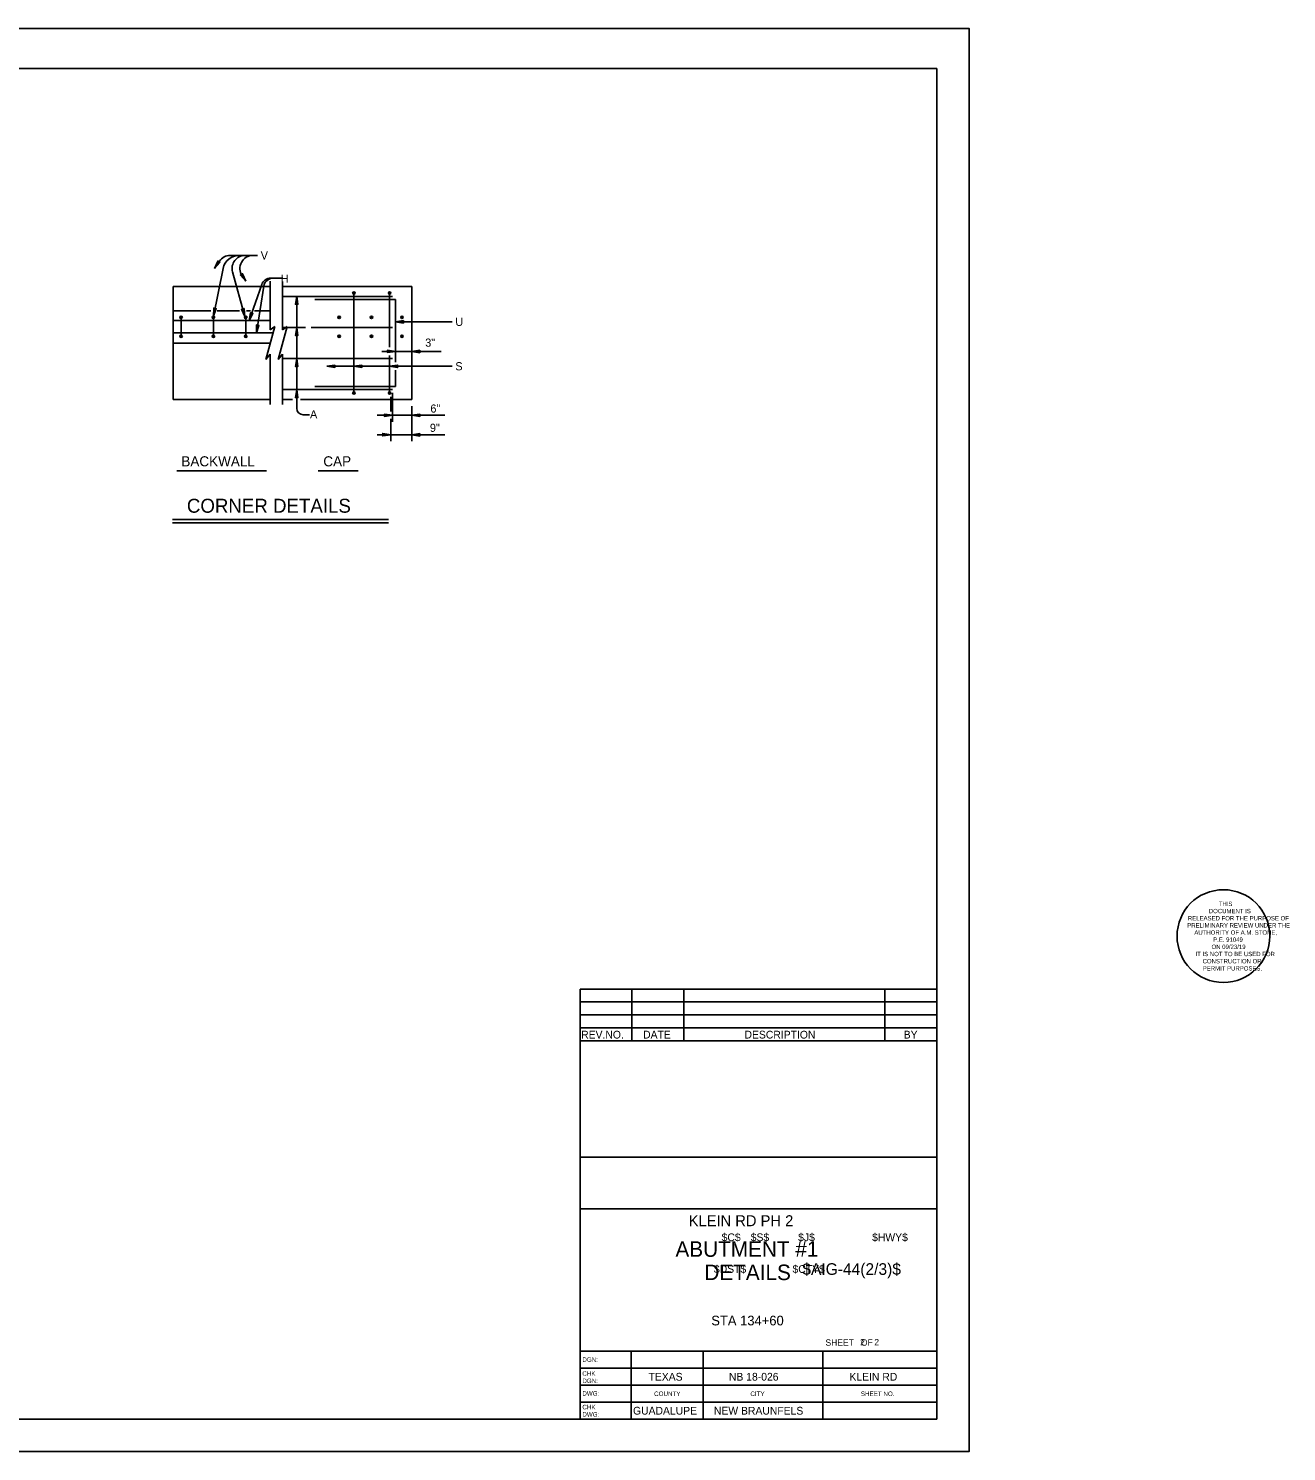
# Model space of a CAD drawing. Extents: x 970 to 1074, y 989 to 1045.
# Drawn here: x 1054.46 to 1073.91, y 997.81 to 1019.81 of the extents above; entities that cross this region are included whole.
import ezdxf

# ---------------------------------------------------------------- set-up
doc = ezdxf.new("R2010")
doc.units = 0
for name, color, linetype in [('BORD_lines_major', 7, 'Continuous'), ('BORD_lines_minor', 7, 'Continuous'), ('BORD_text_large_1', 7, 'Continuous'), ('BORD_text_large_2', 7, 'Continuous'), ('BORD_text_small_1', 7, 'Continuous'), ('BORD_text_small_3', 7, 'Continuous'), ('BORD_text_small_proj', 7, 'Continuous'), ('C-MS-ANNO-TTLB-STMP', 7, 'Continuous'), ('D_BATCH_PLOT', 7, 'Continuous'), ('D_SHEET', 7, 'Continuous'), ('D_SHEET_NUM_CODE', 7, 'Continuous'), ('D_SHEET_TXT_SUB_CODE', 7, 'Continuous'), ('Working Level 1', 7, 'Continuous')]:
    doc.layers.add(name, color=color, linetype=linetype)

msp = doc.modelspace()

# ---------------------------------------------------------------- linework, layer by layer
at = {"layer": 'BORD_lines_major'}
for p, q in [((1037.413, 1019.195), (1068.5, 1019.195)), ((1068.5, 998.313), (1068.5, 1019.195)), ((1037.413, 998.313), (1068.5, 998.313))]:
    msp.add_line(p, q, dxfattribs=at)
at = {"layer": 'BORD_lines_minor'}
for p, q in [((1062.988, 1004.963), (1068.5, 1004.963)), ((1062.988, 1004.163), (1062.988, 1004.963)), ((1063.788, 1004.963), (1063.788, 1004.163)), ((1064.588, 1004.963), (1064.588, 1004.163)), ((1067.7, 1004.163), (1067.7, 1004.963)), ((1062.988, 1004.763), (1068.5, 1004.763)), ((1062.988, 1004.563), (1068.5, 1004.563)), ((1062.988, 1004.363), (1068.5, 1004.363)), ((1062.988, 1004.163), (1068.5, 1004.163)), ((1062.988, 1004.163), (1062.988, 1002.363)), ((1062.988, 1002.363), (1068.5, 1002.363)), ((1062.988, 1002.363), (1062.988, 998.313)), ((1062.988, 1001.563), (1068.5, 1001.563)), ((1062.988, 999.363), (1068.5, 999.363)), ((1063.776, 999.363), (1063.776, 998.313)), ((1064.888, 999.363), (1064.888, 998.313)), ((1066.738, 999.363), (1066.738, 998.313)), ((1062.988, 999.1), (1068.5, 999.1)), ((1062.988, 998.838), (1068.5, 998.838)), ((1062.988, 998.575), (1068.5, 998.575))]:
    msp.add_line(p, q, dxfattribs=at)
at = {"layer": 'C-MS-ANNO-TTLB-STMP'}
msp.add_circle((1072.934, 1005.781), 0.717, dxfattribs=at)
at = {"layer": 'D_BATCH_PLOT'}
msp.add_lwpolyline([(1035, 997.813), (1069, 997.813), (1069, 1019.813), (1035, 1019.813)], close=True, dxfattribs=at)
at = {"layer": 'D_SHEET'}
for p, q in [((1035, 1019.813), (1069, 1019.813)), ((1069, 997.813), (1069, 1019.813)), ((1035, 997.813), (1069, 997.813))]:
    msp.add_line(p, q, dxfattribs=at)
at = {"layer": 'Working Level 1'}
for p, q in [((1057.33, 1016.103), (1057.409, 1016.218)), ((1057.574, 1016.304), (1057.995, 1016.304)), ((1057.315, 1015.365), (1057.466, 1016.104)), ((1057.611, 1016.051), (1057.803, 1015.359)), ((1057.818, 1015.908), (1057.761, 1015.991)), ((1056.692, 1014.075), (1056.692, 1015.825)), ((1058.192, 1015.825), (1056.692, 1015.825)), ((1057.867, 1015.296), (1058.062, 1015.854)), ((1057.979, 1015.105), (1058.094, 1015.828)), ((1058.192, 1015.155), (1058.192, 1015.904)), ((1058.388, 1015.954), (1058.242, 1015.954)), ((1058.385, 1015.155), (1058.385, 1015.903)), ((1058.385, 1015.825), (1060.385, 1015.825)), ((1060.385, 1014.075), (1060.385, 1015.825)), ((1058.385, 1015.671), (1060.085, 1015.671)), ((1058.604, 1013.941), (1058.604, 1015.671)), ((1058.881, 1015.621), (1060.131, 1015.621)), ((1059.487, 1015.721), (1059.487, 1014.18)), ((1060.039, 1015.721), (1060.039, 1014.885)), ((1060.131, 1015.621), (1060.131, 1014.656)), ((1057.276, 1015.45), (1056.692, 1015.45)), ((1056.817, 1015.055), (1056.817, 1015.346)), ((1057.317, 1015.055), (1057.317, 1015.346)), ((1057.718, 1015.45), (1057.374, 1015.45)), ((1057.817, 1015.055), (1057.817, 1015.346)), ((1057.891, 1015.45), (1057.826, 1015.45)), ((1058.192, 1015.45), (1057.949, 1015.45)), ((1058.192, 1015.296), (1056.692, 1015.296)), ((1058.237, 1015.105), (1056.692, 1015.105)), ((1058.126, 1014.695), (1058.264, 1015.207)), ((1058.264, 1015.207), (1058.192, 1015.155)), ((1058.319, 1014.695), (1058.457, 1015.207)), ((1058.457, 1015.207), (1058.385, 1015.155)), ((1058.385, 1015.191), (1058.435, 1015.191)), ((1058.453, 1015.191), (1058.74, 1015.191)), ((1058.829, 1015.191), (1060.085, 1015.191)), ((1060.131, 1015.277), (1061.009, 1015.277)), ((1058.195, 1014.95), (1056.692, 1014.95)), ((1058.192, 1014.775), (1058.126, 1014.695)), ((1058.192, 1013.997), (1058.192, 1014.775)), ((1058.385, 1014.775), (1058.319, 1014.695)), ((1058.385, 1013.997), (1058.385, 1014.775)), ((1058.385, 1014.71), (1060.085, 1014.71)), ((1060.835, 1014.82), (1059.92, 1014.82)), ((1060.039, 1014.757), (1060.039, 1014.18)), ((1059.068, 1014.591), (1061.009, 1014.591)), ((1060.131, 1014.532), (1060.131, 1014.28)), ((1058.385, 1014.23), (1060.085, 1014.23)), ((1058.881, 1014.28), (1060.131, 1014.28)), ((1058.192, 1014.075), (1056.692, 1014.075)), ((1058.385, 1014.075), (1058.539, 1014.075)), ((1058.663, 1014.075), (1060.385, 1014.075)), ((1060.058, 1014.12), (1060.058, 1013.893)), ((1060.085, 1014.182), (1060.085, 1013.732)), ((1058.704, 1013.841), (1058.803, 1013.841)), ((1060.892, 1013.832), (1059.848, 1013.832)), ((1060.058, 1013.776), (1060.058, 1013.432)), ((1060.385, 1013.975), (1060.385, 1013.432)), ((1060.892, 1013.532), (1059.848, 1013.532)), ((1056.751, 1012.975), (1058.135, 1012.975)), ((1058.933, 1012.975), (1059.555, 1012.975)), ((1056.681, 1012.221), (1060.025, 1012.221)), ((1056.681, 1012.171), (1060.025, 1012.171))]:
    msp.add_line(p, q, dxfattribs=at)
for points in [[(1057.33, 1016.103), (1057.383, 1016.216), (1057.415, 1016.194)], [(1057.818, 1015.908), (1057.765, 1016.021), (1057.733, 1015.999)], [(1058.604, 1015.671), (1058.584, 1015.549), (1058.623, 1015.549)], [(1057.315, 1015.365), (1057.359, 1015.481), (1057.321, 1015.489)], [(1057.803, 1015.359), (1057.79, 1015.483), (1057.752, 1015.472)], [(1057.867, 1015.296), (1057.926, 1015.405), (1057.89, 1015.418)], [(1057.979, 1015.105), (1058.018, 1015.222), (1057.98, 1015.229)], [(1058.604, 1015.191), (1058.584, 1015.068), (1058.623, 1015.068)], [(1060.131, 1015.277), (1060.253, 1015.257), (1060.253, 1015.296)], [(1058.604, 1014.71), (1058.584, 1014.588), (1058.623, 1014.588)], [(1060.131, 1014.82), (1060.008, 1014.84), (1060.008, 1014.801)], [(1060.385, 1014.82), (1060.507, 1014.8), (1060.507, 1014.838)], [(1059.068, 1014.591), (1059.191, 1014.571), (1059.191, 1014.61)], [(1059.487, 1014.591), (1059.609, 1014.571), (1059.609, 1014.61)], [(1060.039, 1014.591), (1060.162, 1014.571), (1060.162, 1014.61)], [(1058.604, 1014.23), (1058.584, 1014.107), (1058.623, 1014.107)], [(1060.085, 1013.832), (1059.962, 1013.852), (1059.962, 1013.813)], [(1060.385, 1013.832), (1060.507, 1013.812), (1060.507, 1013.851)], [(1060.058, 1013.532), (1059.935, 1013.552), (1059.935, 1013.513)], [(1060.385, 1013.532), (1060.507, 1013.512), (1060.507, 1013.551)]]:
    msp.add_lwpolyline(points, close=True, dxfattribs=at)
for centre, radius in [((1059.487, 1015.721), 0.0187), ((1060.039, 1015.721), 0.0187), ((1059.487, 1015.721), 0.0117), ((1059.487, 1015.721), 0.00469), ((1060.039, 1015.721), 0.0117), ((1060.039, 1015.721), 0.00469), ((1056.816, 1015.346), 0.0187), ((1056.816, 1015.346), 0.0117), ((1056.816, 1015.346), 0.00469), ((1057.316, 1015.346), 0.0187), ((1057.316, 1015.346), 0.0117), ((1057.316, 1015.346), 0.00469), ((1057.816, 1015.346), 0.0187), ((1057.816, 1015.346), 0.0117), ((1057.816, 1015.346), 0.00469), ((1059.26, 1015.346), 0.0187), ((1059.26, 1015.346), 0.0117), ((1059.26, 1015.346), 0.00469), ((1059.76, 1015.346), 0.0187), ((1059.76, 1015.346), 0.0117), ((1059.76, 1015.346), 0.00469), ((1060.231, 1015.346), 0.0187), ((1060.231, 1015.346), 0.0117), ((1060.231, 1015.346), 0.00469), ((1056.816, 1015.055), 0.0187), ((1056.816, 1015.055), 0.0117), ((1056.816, 1015.055), 0.00469), ((1057.316, 1015.055), 0.0187), ((1057.316, 1015.055), 0.0117), ((1057.316, 1015.055), 0.00469), ((1057.816, 1015.055), 0.0187), ((1057.816, 1015.055), 0.0117), ((1057.816, 1015.055), 0.00469), ((1059.26, 1015.055), 0.0187), ((1059.26, 1015.055), 0.0117), ((1059.26, 1015.055), 0.00469), ((1059.76, 1015.055), 0.0187), ((1059.76, 1015.055), 0.0117), ((1059.76, 1015.055), 0.00469), ((1060.231, 1015.055), 0.0187), ((1060.231, 1015.055), 0.0187), ((1060.231, 1015.055), 0.0117), ((1060.231, 1015.055), 0.0117), ((1060.231, 1015.055), 0.00469), ((1060.231, 1015.055), 0.00469), ((1059.487, 1014.179), 0.0187), ((1060.039, 1014.179), 0.0187), ((1059.487, 1014.179), 0.0117), ((1059.487, 1014.179), 0.00469), ((1060.039, 1014.179), 0.0117), ((1060.039, 1014.179), 0.00469)]:
    msp.add_circle(centre, radius, dxfattribs=at)
for centre, radius, start, end in [((1057.574, 1016.104), 0.2, 90, 145.4917), ((1057.711, 1016.054), 0.25, 90, 168.4552), ((1057.804, 1016.104), 0.2, 90, 195.5006), ((1057.925, 1016.104), 0.2, 90, 214.524), ((1058.203, 1015.804), 0.15, 90, 160.7438), ((1058.242, 1015.804), 0.15, 90, 170.9957), ((1058.704, 1013.941), 0.1, 180, 270)]:
    msp.add_arc(centre, radius, start, end, dxfattribs=at)

# ---------------------------------------------------------------- texts
at = {"layer": 'BORD_lines_minor'}
for s, p in [('REV.NO.', (1063.002, 1004.198)), ('DATE', (1063.96, 1004.198)), ('DESCRIPTION', (1065.528, 1004.198)), ('BY', (1067.99, 1004.198))]:
    msp.add_text(s, height=0.12, rotation=359.9834, dxfattribs=at).set_placement(p)
msp.add_text('KLEIN RD PH 2', height=0.17, dxfattribs=at).set_placement((1064.665, 1001.296))
at = {"layer": 'BORD_text_large_1'}
for s, p in [('ABUTMENT #1', (1064.46, 1000.823)), ('DETAILS', (1064.907, 1000.463))]:
    msp.add_text(s, height=0.24, dxfattribs=at).set_placement(p)
at = {"layer": 'BORD_text_large_2'}
msp.add_text('STA 134+60', height=0.15, dxfattribs=at).set_placement((1065.014, 999.763))
at = {"layer": 'BORD_text_small_1'}
msp.add_text('SHEET   OF', height=0.0984, dxfattribs=at).set_placement((1066.78, 999.449))
at = {"layer": 'BORD_text_small_3'}
msp.add_text('2    2', height=0.0984, dxfattribs=at).set_placement((1067.316, 999.455))
at = {"layer": 'BORD_text_small_proj'}
for s, height, p in [('DGN:', 0.07, (1063.02, 999.199)), ('CHK', 0.07, (1063.02, 998.984)), ('TEXAS', 0.12, (1064.044, 998.909)), ('KLEIN RD', 0.12, (1067.151, 998.909)), ('DGN:', 0.07, (1063.02, 998.871)), ('DWG:', 0.07, (1063.02, 998.677)), ('COUNTY', 0.07, (1064.13, 998.671)), ('CITY', 0.07, (1065.619, 998.671)), ('SHEET NO.', 0.07, (1067.327, 998.671)), ('CHK', 0.07, (1063.02, 998.465)), ('DWG:', 0.07, (1063.02, 998.352)), ('GUADALUPE', 0.12, (1063.804, 998.384)), ('NEW BRAUNFELS', 0.12, (1065.055, 998.384))]:
    msp.add_text(s, height=height, rotation=359.9834, dxfattribs=at).set_placement(p)
msp.add_text('NB 18-026', height=0.12, dxfattribs=at).set_placement((1065.287, 998.909))
at = {"layer": 'C-MS-ANNO-TTLB-STMP'}
for s, height, p in [('THIS', 0.0672, (1072.861, 1006.246)), ('RELEASED FOR THE PURPOSE OF', 0.06723, (1072.384, 1006.024)), ('DOCUMENT IS', 0.06723, (1072.708, 1006.135)), ('PRELIMINARY REVIEW UNDER THE', 0.06723, (1072.375, 1005.914)), ('AUTHORITY OF A.M. STONE,', 0.06723, (1072.484, 1005.803)), ('ON 09/23/19', 0.06723, (1072.75, 1005.582)), ('P.E. 91049', 0.0672, (1072.775, 1005.693)), ('IT IS NOT TO BE USED FOR', 0.06723, (1072.502, 1005.471)), ('CONSTRUCTION OR', 0.06723, (1072.612, 1005.36)), ('PERMIT PURPOSES.', 0.06723, (1072.614, 1005.249))]:
    msp.add_text(s, height=height, rotation=360, dxfattribs=at).set_placement(p)
at = {"layer": 'D_SHEET_NUM_CODE'}
msp.add_text('$AIG-44(2/3)$', height=0.18, dxfattribs=at).set_placement((1066.422, 1000.544))
at = {"layer": 'D_SHEET_TXT_SUB_CODE'}
for s, p in [('$C$', (1065.174, 1001.065)), ('$S$', (1065.624, 1001.065)), ('$J$', (1066.357, 1001.065)), ('$HWY$', (1067.501, 1001.065)), ('$DST$', (1065.055, 1000.574)), ('$CTY$', (1066.27, 1000.574))]:
    msp.add_text(s, height=0.12, dxfattribs=at).set_placement(p)
at = {"layer": 'Working Level 1'}
for s, height, p in [('V', 0.126, (1058.046, 1016.241)), (' H', 0.126, (1058.309, 1015.882)), (' U', 0.126, (1061.009, 1015.214)), ('3"', 0.126, (1060.591, 1014.893)), (' S', 0.126, (1061.009, 1014.528)), ('6"', 0.126, (1060.67, 1013.874)), (' A', 0.126, (1058.762, 1013.785)), ('9"', 0.126, (1060.663, 1013.576)), ('BACKWALL', 0.156, (1056.82, 1013.043)), ('CAP', 0.156, (1059.015, 1013.043)), ('CORNER DETAILS', 0.216, (1056.905, 1012.326))]:
    msp.add_text(s, height=height, dxfattribs=at).set_placement(p)

doc.saveas('drawing.dxf')
